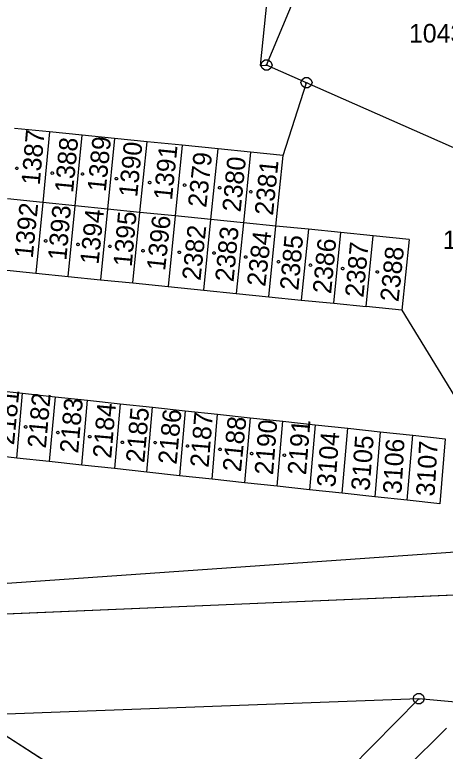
# Model space of a CAD drawing. Extents: x -777309 to -774195, y -1144706 to -1143600.
# Drawn here: x -775133.6 to -775094.2, y -1144462.3 to -1144394.9 of the extents above; entities that cross this region are included whole.
import ezdxf

# ---------------------------------------------------------------- set-up
doc = ezdxf.new("R2010")
doc.units = 0
for name, color, linetype in [('1', 7, 'Continuous'), ('11', 7, 'Continuous'), ('12', 7, 'Continuous'), ('2', 7, 'Continuous'), ('4', 7, 'Continuous'), ('5', 7, 'Continuous'), ('8', 7, 'Continuous')]:
    doc.layers.add(name, color=color, linetype=linetype)

msp = doc.modelspace()

# ---------------------------------------------------------------- linework, layer by layer
at = {"layer": '1'}
for p, q in [((-775110.57, -1144399.52), (-775105.05, -1144386.27)), ((-775110.56, -1144393.59), (-775111.16, -1144399.56)), ((-775111.16, -1144399.56), (-775110.57, -1144399.52)), ((-775106.91, -1144401.13), (-775110.57, -1144399.52)), ((-775109.06, -1144407.78), (-775106.91, -1144401.13)), ((-775080.73, -1144412.7), (-775106.91, -1144401.13)), ((-775130.42, -1144405.63), (-775133.63, -1144405.31)), ((-775130.42, -1144405.63), (-775131.06, -1144412.09)), ((-775127.45, -1144405.93), (-775130.42, -1144405.63)), ((-775128.09, -1144412.39), (-775127.45, -1144405.93)), ((-775124.49, -1144406.23), (-775127.45, -1144405.93)), ((-775124.49, -1144406.23), (-775125.13, -1144412.69)), ((-775121.51, -1144406.53), (-775124.49, -1144406.23)), ((-775122.16, -1144412.99), (-775121.51, -1144406.53)), ((-775118.28, -1144406.85), (-775121.51, -1144406.53)), ((-775118.28, -1144406.85), (-775118.93, -1144413.31)), ((-775115.01, -1144407.18), (-775118.28, -1144406.85)), ((-775115.66, -1144413.64), (-775115.01, -1144407.18)), ((-775112.03, -1144407.48), (-775115.01, -1144407.18)), ((-775112.03, -1144407.48), (-775112.69, -1144413.94)), ((-775109.06, -1144407.78), (-775112.03, -1144407.48)), ((-775109.71, -1144414.24), (-775109.06, -1144407.78)), ((-775131.06, -1144412.09), (-775134.27, -1144411.76)), ((-775131.06, -1144412.09), (-775131.7, -1144418.54)), ((-775128.09, -1144412.39), (-775131.06, -1144412.09)), ((-775128.74, -1144418.85), (-775128.09, -1144412.39)), ((-775125.13, -1144412.69), (-775128.09, -1144412.39)), ((-775125.13, -1144412.69), (-775125.77, -1144419.15)), ((-775122.16, -1144412.99), (-775125.13, -1144412.69)), ((-775122.8, -1144419.45), (-775122.16, -1144412.99)), ((-775118.93, -1144413.31), (-775122.16, -1144412.99)), ((-775118.93, -1144413.31), (-775119.58, -1144419.77)), ((-775115.66, -1144413.64), (-775118.93, -1144413.31)), ((-775116.31, -1144420.1), (-775115.66, -1144413.64)), ((-775112.69, -1144413.94), (-775115.66, -1144413.64)), ((-775112.69, -1144413.94), (-775113.34, -1144420.4)), ((-775109.71, -1144414.24), (-775112.69, -1144413.94)), ((-775110.37, -1144420.71), (-775109.71, -1144414.24)), ((-775106.74, -1144414.54), (-775109.71, -1144414.24)), ((-775106.74, -1144414.54), (-775107.39, -1144421.01)), ((-775103.77, -1144414.84), (-775106.74, -1144414.54)), ((-775104.42, -1144421.31), (-775103.77, -1144414.84)), ((-775100.8, -1144415.14), (-775103.77, -1144414.84)), ((-775101.45, -1144421.61), (-775100.8, -1144415.14)), ((-775097.53, -1144415.47), (-775100.8, -1144415.14)), ((-775097.53, -1144415.47), (-775098.18, -1144421.94)), ((-775134.91, -1144418.22), (-775131.7, -1144418.54)), ((-775131.7, -1144418.54), (-775128.74, -1144418.85)), ((-775128.74, -1144418.85), (-775125.77, -1144419.15)), ((-775125.77, -1144419.15), (-775122.8, -1144419.45)), ((-775122.8, -1144419.45), (-775119.58, -1144419.77)), ((-775119.58, -1144419.77), (-775116.31, -1144420.1)), ((-775116.31, -1144420.1), (-775113.34, -1144420.4)), ((-775113.34, -1144420.4), (-775110.37, -1144420.71)), ((-775110.37, -1144420.71), (-775107.39, -1144421.01)), ((-775107.39, -1144421.01), (-775104.42, -1144421.31)), ((-775104.42, -1144421.31), (-775101.45, -1144421.61)), ((-775098.18, -1144421.94), (-775101.45, -1144421.61)), ((-775098.18, -1144421.94), (-775093.37, -1144429.8)), ((-775135.87, -1144429.22), (-775132.9, -1144429.54)), ((-775133.43, -1144435.48), (-775132.9, -1144429.54)), ((-775132.9, -1144429.54), (-775129.92, -1144429.86)), ((-775129.92, -1144429.86), (-775130.46, -1144435.8)), ((-775129.92, -1144429.86), (-775126.95, -1144430.18)), ((-775127.48, -1144436.12), (-775126.95, -1144430.18)), ((-775126.95, -1144430.18), (-775123.97, -1144430.5)), ((-775123.97, -1144430.5), (-775124.5, -1144436.44)), ((-775123.97, -1144430.5), (-775121, -1144430.82)), ((-775121.52, -1144436.76), (-775121, -1144430.82)), ((-775121, -1144430.82), (-775118.02, -1144431.14)), ((-775118.02, -1144431.14), (-775118.54, -1144437.09)), ((-775118.02, -1144431.14), (-775115.05, -1144431.46)), ((-775115.56, -1144437.41), (-775115.05, -1144431.46)), ((-775115.05, -1144431.46), (-775112.07, -1144431.78)), ((-775112.07, -1144431.78), (-775112.58, -1144437.73)), ((-775112.07, -1144431.78), (-775109.09, -1144432.1)), ((-775109.61, -1144438.05), (-775109.09, -1144432.1)), ((-775109.09, -1144432.1), (-775106.12, -1144432.42)), ((-775106.12, -1144432.42), (-775106.63, -1144438.37)), ((-775106.12, -1144432.42), (-775103.14, -1144432.74)), ((-775103.65, -1144438.7), (-775103.14, -1144432.74)), ((-775103.14, -1144432.74), (-775100.17, -1144433.06)), ((-775100.17, -1144433.06), (-775100.67, -1144439.02)), ((-775100.17, -1144433.06), (-775097.19, -1144433.38)), ((-775097.69, -1144439.34), (-775097.19, -1144433.38)), ((-775097.19, -1144433.38), (-775094.22, -1144433.7)), ((-775094.22, -1144433.7), (-775094.71, -1144439.66)), ((-775133.43, -1144435.48), (-775136.41, -1144435.15)), ((-775130.46, -1144435.8), (-775133.43, -1144435.48)), ((-775127.48, -1144436.12), (-775130.46, -1144435.8)), ((-775124.5, -1144436.44), (-775127.48, -1144436.12)), ((-775121.52, -1144436.76), (-775124.5, -1144436.44)), ((-775118.54, -1144437.09), (-775121.52, -1144436.76)), ((-775115.56, -1144437.41), (-775118.54, -1144437.09)), ((-775112.58, -1144437.73), (-775115.56, -1144437.41)), ((-775109.61, -1144438.05), (-775112.58, -1144437.73)), ((-775106.63, -1144438.37), (-775109.61, -1144438.05)), ((-775103.65, -1144438.7), (-775106.63, -1144438.37)), ((-775100.67, -1144439.02), (-775103.65, -1144438.7)), ((-775097.69, -1144439.34), (-775100.67, -1144439.02)), ((-775094.71, -1144439.66), (-775097.69, -1144439.34)), ((-775157.8, -1144448.55), (-775092.84, -1144444.02)), ((-775088.39, -1144447.82), (-775138.01, -1144449.91)), ((-775096.64, -1144457.51), (-775137.35, -1144459.01)), ((-775113.36, -1144474.42), (-775096.64, -1144457.51)), ((-775076.86, -1144459.23), (-775096.64, -1144457.51)), ((-775137.35, -1144459.01), (-775115.39, -1144473.12))]:
    msp.add_line(p, q, dxfattribs=at)
at = {"layer": '11'}
for points in [[(-774795.44, -1144408.94), (-774821.85, -1144410.67), (-774824.22, -1144416.24), (-774826.54, -1144421.73), (-774829.24, -1144428.08), (-774832.66, -1144428.33), (-774870.21, -1144431.11), (-774871.96, -1144431.24), (-774890.46, -1144432.61), (-774957.77, -1144437.47), (-775003.31, -1144440.57), (-775006.9, -1144440.82), (-775032.95, -1144440.83), (-775037.63, -1144440.85), (-775036.16, -1144437.94), (-775069.78, -1144440.38), (-775071.04, -1144440.88), (-775088.39, -1144447.82), (-775138.01, -1144449.91)], [(-775137.35, -1144459.01), (-775115.39, -1144473.12), (-775113.36, -1144474.42), (-775120.76, -1144481.29), (-775159.15, -1144509.7)]]:
    msp.add_lwpolyline(points, dxfattribs=at)
at = {"layer": '12'}
for p, q in [((-775130.42, -1144405.63), (-775133.63, -1144405.31)), ((-775130.42, -1144405.63), (-775131.06, -1144412.09)), ((-775130.42, -1144405.63), (-775131.06, -1144412.09)), ((-775127.45, -1144405.93), (-775130.42, -1144405.63)), ((-775128.09, -1144412.39), (-775127.45, -1144405.93)), ((-775128.09, -1144412.39), (-775127.45, -1144405.93)), ((-775124.49, -1144406.23), (-775127.45, -1144405.93)), ((-775124.49, -1144406.23), (-775125.13, -1144412.69)), ((-775124.49, -1144406.23), (-775125.13, -1144412.69)), ((-775121.51, -1144406.53), (-775124.49, -1144406.23)), ((-775122.16, -1144412.99), (-775121.51, -1144406.53)), ((-775122.16, -1144412.99), (-775121.51, -1144406.53)), ((-775118.28, -1144406.85), (-775121.51, -1144406.53)), ((-775118.28, -1144406.85), (-775118.93, -1144413.31)), ((-775118.28, -1144406.85), (-775118.93, -1144413.31)), ((-775115.01, -1144407.18), (-775118.28, -1144406.85)), ((-775115.66, -1144413.64), (-775115.01, -1144407.18)), ((-775115.66, -1144413.64), (-775115.01, -1144407.18)), ((-775112.03, -1144407.48), (-775115.01, -1144407.18)), ((-775112.03, -1144407.48), (-775112.69, -1144413.94)), ((-775112.03, -1144407.48), (-775112.69, -1144413.94)), ((-775109.06, -1144407.78), (-775112.03, -1144407.48)), ((-775109.71, -1144414.24), (-775109.06, -1144407.78)), ((-775131.06, -1144412.09), (-775134.27, -1144411.76)), ((-775131.06, -1144412.09), (-775134.27, -1144411.76)), ((-775131.06, -1144412.09), (-775131.7, -1144418.54)), ((-775131.06, -1144412.09), (-775131.7, -1144418.54)), ((-775128.09, -1144412.39), (-775131.06, -1144412.09)), ((-775128.09, -1144412.39), (-775131.06, -1144412.09)), ((-775128.74, -1144418.85), (-775128.09, -1144412.39)), ((-775128.74, -1144418.85), (-775128.09, -1144412.39)), ((-775125.13, -1144412.69), (-775128.09, -1144412.39)), ((-775125.13, -1144412.69), (-775128.09, -1144412.39)), ((-775125.13, -1144412.69), (-775125.77, -1144419.15)), ((-775125.13, -1144412.69), (-775125.77, -1144419.15)), ((-775122.16, -1144412.99), (-775125.13, -1144412.69)), ((-775122.16, -1144412.99), (-775125.13, -1144412.69)), ((-775122.8, -1144419.45), (-775122.16, -1144412.99)), ((-775122.8, -1144419.45), (-775122.16, -1144412.99)), ((-775118.93, -1144413.31), (-775122.16, -1144412.99)), ((-775118.93, -1144413.31), (-775122.16, -1144412.99)), ((-775118.93, -1144413.31), (-775119.58, -1144419.77)), ((-775118.93, -1144413.31), (-775119.58, -1144419.77)), ((-775115.66, -1144413.64), (-775118.93, -1144413.31)), ((-775115.66, -1144413.64), (-775118.93, -1144413.31)), ((-775116.31, -1144420.1), (-775115.66, -1144413.64)), ((-775116.31, -1144420.1), (-775115.66, -1144413.64)), ((-775112.69, -1144413.94), (-775115.66, -1144413.64)), ((-775112.69, -1144413.94), (-775115.66, -1144413.64)), ((-775112.69, -1144413.94), (-775113.34, -1144420.4)), ((-775112.69, -1144413.94), (-775113.34, -1144420.4)), ((-775109.71, -1144414.24), (-775112.69, -1144413.94)), ((-775109.71, -1144414.24), (-775112.69, -1144413.94)), ((-775110.37, -1144420.71), (-775109.71, -1144414.24)), ((-775110.37, -1144420.71), (-775109.71, -1144414.24)), ((-775106.74, -1144414.54), (-775109.71, -1144414.24)), ((-775106.74, -1144414.54), (-775107.39, -1144421.01)), ((-775106.74, -1144414.54), (-775107.39, -1144421.01)), ((-775103.77, -1144414.84), (-775106.74, -1144414.54)), ((-775104.42, -1144421.31), (-775103.77, -1144414.84)), ((-775104.42, -1144421.31), (-775103.77, -1144414.84)), ((-775100.8, -1144415.14), (-775103.77, -1144414.84)), ((-775101.45, -1144421.61), (-775100.8, -1144415.14)), ((-775101.45, -1144421.61), (-775100.8, -1144415.14)), ((-775097.53, -1144415.47), (-775100.8, -1144415.14)), ((-775097.53, -1144415.47), (-775098.18, -1144421.94)), ((-775134.91, -1144418.22), (-775131.7, -1144418.54)), ((-775131.7, -1144418.54), (-775128.74, -1144418.85)), ((-775128.74, -1144418.85), (-775125.77, -1144419.15)), ((-775125.77, -1144419.15), (-775122.8, -1144419.45)), ((-775122.8, -1144419.45), (-775119.58, -1144419.77)), ((-775119.58, -1144419.77), (-775116.31, -1144420.1)), ((-775116.31, -1144420.1), (-775113.34, -1144420.4)), ((-775113.34, -1144420.4), (-775110.37, -1144420.71)), ((-775110.37, -1144420.71), (-775107.39, -1144421.01)), ((-775107.39, -1144421.01), (-775104.42, -1144421.31)), ((-775104.42, -1144421.31), (-775101.45, -1144421.61)), ((-775098.18, -1144421.94), (-775101.45, -1144421.61)), ((-775135.87, -1144429.22), (-775132.9, -1144429.54)), ((-775133.43, -1144435.48), (-775132.9, -1144429.54)), ((-775133.43, -1144435.48), (-775132.9, -1144429.54)), ((-775132.9, -1144429.54), (-775129.92, -1144429.86)), ((-775129.92, -1144429.86), (-775130.46, -1144435.8)), ((-775129.92, -1144429.86), (-775130.46, -1144435.8)), ((-775129.92, -1144429.86), (-775126.95, -1144430.18)), ((-775127.48, -1144436.12), (-775126.95, -1144430.18)), ((-775127.48, -1144436.12), (-775126.95, -1144430.18)), ((-775126.95, -1144430.18), (-775123.97, -1144430.5)), ((-775123.97, -1144430.5), (-775124.5, -1144436.44)), ((-775123.97, -1144430.5), (-775124.5, -1144436.44)), ((-775123.97, -1144430.5), (-775121, -1144430.82)), ((-775121.52, -1144436.76), (-775121, -1144430.82)), ((-775121.52, -1144436.76), (-775121, -1144430.82)), ((-775121, -1144430.82), (-775118.02, -1144431.14)), ((-775118.02, -1144431.14), (-775118.54, -1144437.09)), ((-775118.02, -1144431.14), (-775118.54, -1144437.09)), ((-775118.02, -1144431.14), (-775115.05, -1144431.46)), ((-775115.56, -1144437.41), (-775115.05, -1144431.46)), ((-775115.56, -1144437.41), (-775115.05, -1144431.46)), ((-775115.05, -1144431.46), (-775112.07, -1144431.78)), ((-775112.07, -1144431.78), (-775112.58, -1144437.73)), ((-775112.07, -1144431.78), (-775112.58, -1144437.73)), ((-775112.07, -1144431.78), (-775109.09, -1144432.1)), ((-775109.61, -1144438.05), (-775109.09, -1144432.1)), ((-775109.61, -1144438.05), (-775109.09, -1144432.1)), ((-775109.09, -1144432.1), (-775106.12, -1144432.42)), ((-775106.12, -1144432.42), (-775106.63, -1144438.37)), ((-775133.43, -1144435.48), (-775136.41, -1144435.15)), ((-775130.46, -1144435.8), (-775133.43, -1144435.48)), ((-775127.48, -1144436.12), (-775130.46, -1144435.8)), ((-775124.5, -1144436.44), (-775127.48, -1144436.12)), ((-775121.52, -1144436.76), (-775124.5, -1144436.44)), ((-775118.54, -1144437.09), (-775121.52, -1144436.76)), ((-775115.56, -1144437.41), (-775118.54, -1144437.09)), ((-775112.58, -1144437.73), (-775115.56, -1144437.41)), ((-775109.61, -1144438.05), (-775112.58, -1144437.73)), ((-775106.63, -1144438.37), (-775109.61, -1144438.05))]:
    msp.add_line(p, q, dxfattribs=at)
at = {"layer": '4'}
msp.add_line((-775094.1, -1144460.2), (-775111.21, -1144477.04), dxfattribs=at)
at = {"layer": '5'}
for points in [[(-775133.43, -1144408.846), (-775133.363, -1144408.86), (-775133.329, -1144408.92), (-775133.316, -1144408.96), (-775133.329, -1144409.02), (-775133.383, -1144409.067), (-775133.43, -1144409.074), (-775133.49, -1144409.054), (-775133.531, -1144409.014), (-775133.544, -1144408.96), (-775133.531, -1144408.9), (-775133.477, -1144408.853)], [(-775130.18, -1144409.286), (-775130.113, -1144409.299), (-775130.079, -1144409.36), (-775130.066, -1144409.4), (-775130.079, -1144409.46), (-775130.133, -1144409.507), (-775130.18, -1144409.514), (-775130.24, -1144409.494), (-775130.281, -1144409.454), (-775130.294, -1144409.4), (-775130.281, -1144409.34), (-775130.227, -1144409.293)], [(-775127.41, -1144409.366), (-775127.343, -1144409.38), (-775127.309, -1144409.44), (-775127.296, -1144409.48), (-775127.309, -1144409.54), (-775127.363, -1144409.587), (-775127.41, -1144409.594), (-775127.47, -1144409.574), (-775127.511, -1144409.534), (-775127.524, -1144409.48), (-775127.511, -1144409.42), (-775127.457, -1144409.373)], [(-775124.31, -1144409.796), (-775124.243, -1144409.809), (-775124.21, -1144409.87), (-775124.196, -1144409.91), (-775124.21, -1144409.97), (-775124.263, -1144410.017), (-775124.31, -1144410.024), (-775124.37, -1144410.004), (-775124.411, -1144409.964), (-775124.424, -1144409.91), (-775124.411, -1144409.85), (-775124.357, -1144409.803)], [(-775121.27, -1144410.146), (-775121.203, -1144410.16), (-775121.17, -1144410.22), (-775121.156, -1144410.26), (-775121.17, -1144410.32), (-775121.223, -1144410.367), (-775121.27, -1144410.374), (-775121.33, -1144410.354), (-775121.37, -1144410.314), (-775121.384, -1144410.26), (-775121.37, -1144410.2), (-775121.317, -1144410.153)], [(-775118.07, -1144410.386), (-775118.003, -1144410.4), (-775117.969, -1144410.46), (-775117.956, -1144410.5), (-775117.969, -1144410.56), (-775118.023, -1144410.607), (-775118.07, -1144410.614), (-775118.13, -1144410.594), (-775118.171, -1144410.554), (-775118.184, -1144410.5), (-775118.171, -1144410.44), (-775118.117, -1144410.393)], [(-775114.86, -1144410.626), (-775114.793, -1144410.64), (-775114.759, -1144410.7), (-775114.746, -1144410.74), (-775114.759, -1144410.8), (-775114.813, -1144410.847), (-775114.86, -1144410.854), (-775114.92, -1144410.834), (-775114.961, -1144410.794), (-775114.974, -1144410.74), (-775114.961, -1144410.68), (-775114.907, -1144410.633)], [(-775112.01, -1144410.996), (-775111.943, -1144411.01), (-775111.91, -1144411.07), (-775111.896, -1144411.11), (-775111.91, -1144411.17), (-775111.963, -1144411.217), (-775112.01, -1144411.224), (-775112.07, -1144411.204), (-775112.111, -1144411.164), (-775112.124, -1144411.11), (-775112.111, -1144411.05), (-775112.057, -1144411.003)], [(-775130.79, -1144415.486), (-775130.723, -1144415.5), (-775130.69, -1144415.56), (-775130.676, -1144415.6), (-775130.69, -1144415.66), (-775130.743, -1144415.707), (-775130.79, -1144415.714), (-775130.85, -1144415.694), (-775130.891, -1144415.654), (-775130.904, -1144415.6), (-775130.891, -1144415.54), (-775130.837, -1144415.493)], [(-775127.82, -1144415.816), (-775127.753, -1144415.829), (-775127.719, -1144415.89), (-775127.706, -1144415.93), (-775127.719, -1144415.99), (-775127.773, -1144416.037), (-775127.82, -1144416.044), (-775127.88, -1144416.024), (-775127.921, -1144415.984), (-775127.934, -1144415.93), (-775127.921, -1144415.87), (-775127.867, -1144415.823)], [(-775124.91, -1144415.986), (-775124.843, -1144416), (-775124.809, -1144416.06), (-775124.796, -1144416.1), (-775124.809, -1144416.16), (-775124.863, -1144416.207), (-775124.91, -1144416.214), (-775124.97, -1144416.194), (-775125.011, -1144416.154), (-775125.024, -1144416.1), (-775125.011, -1144416.04), (-775124.957, -1144415.993)], [(-775121.87, -1144416.396), (-775121.803, -1144416.41), (-775121.769, -1144416.47), (-775121.756, -1144416.51), (-775121.769, -1144416.57), (-775121.823, -1144416.617), (-775121.87, -1144416.624), (-775121.93, -1144416.604), (-775121.971, -1144416.564), (-775121.984, -1144416.51), (-775121.971, -1144416.45), (-775121.917, -1144416.403)], [(-775118.56, -1144416.526), (-775118.493, -1144416.539), (-775118.46, -1144416.6), (-775118.446, -1144416.64), (-775118.46, -1144416.7), (-775118.513, -1144416.747), (-775118.56, -1144416.754), (-775118.62, -1144416.734), (-775118.66, -1144416.694), (-775118.674, -1144416.64), (-775118.66, -1144416.58), (-775118.607, -1144416.533)], [(-775115.38, -1144416.596), (-775115.313, -1144416.61), (-775115.28, -1144416.67), (-775115.266, -1144416.71), (-775115.28, -1144416.77), (-775115.333, -1144416.817), (-775115.38, -1144416.824), (-775115.44, -1144416.804), (-775115.481, -1144416.764), (-775115.494, -1144416.71), (-775115.481, -1144416.65), (-775115.427, -1144416.603)], [(-775112.48, -1144416.966), (-775112.413, -1144416.98), (-775112.38, -1144417.04), (-775112.366, -1144417.08), (-775112.38, -1144417.14), (-775112.433, -1144417.187), (-775112.48, -1144417.194), (-775112.54, -1144417.174), (-775112.581, -1144417.134), (-775112.594, -1144417.08), (-775112.581, -1144417.02), (-775112.527, -1144416.973)], [(-775109.48, -1144417.396), (-775109.413, -1144417.41), (-775109.38, -1144417.47), (-775109.366, -1144417.51), (-775109.38, -1144417.57), (-775109.433, -1144417.617), (-775109.48, -1144417.624), (-775109.54, -1144417.604), (-775109.581, -1144417.564), (-775109.594, -1144417.51), (-775109.581, -1144417.45), (-775109.527, -1144417.403)], [(-775106.55, -1144417.706), (-775106.483, -1144417.72), (-775106.45, -1144417.78), (-775106.436, -1144417.82), (-775106.45, -1144417.88), (-775106.503, -1144417.927), (-775106.55, -1144417.934), (-775106.61, -1144417.914), (-775106.65, -1144417.874), (-775106.664, -1144417.82), (-775106.65, -1144417.76), (-775106.597, -1144417.713)], [(-775103.61, -1144418.016), (-775103.543, -1144418.029), (-775103.509, -1144418.09), (-775103.496, -1144418.13), (-775103.509, -1144418.19), (-775103.563, -1144418.237), (-775103.61, -1144418.244), (-775103.67, -1144418.224), (-775103.711, -1144418.184), (-775103.724, -1144418.13), (-775103.711, -1144418.07), (-775103.657, -1144418.023)], [(-775100.43, -1144418.326), (-775100.363, -1144418.34), (-775100.329, -1144418.4), (-775100.316, -1144418.44), (-775100.329, -1144418.5), (-775100.383, -1144418.547), (-775100.43, -1144418.554), (-775100.49, -1144418.534), (-775100.531, -1144418.494), (-775100.544, -1144418.44), (-775100.531, -1144418.38), (-775100.477, -1144418.333)], [(-775132.62, -1144432.506), (-775132.553, -1144432.52), (-775132.519, -1144432.58), (-775132.506, -1144432.62), (-775132.519, -1144432.68), (-775132.573, -1144432.727), (-775132.62, -1144432.734), (-775132.68, -1144432.714), (-775132.721, -1144432.674), (-775132.734, -1144432.62), (-775132.721, -1144432.56), (-775132.667, -1144432.513)], [(-775129.67, -1144433.026), (-775129.603, -1144433.039), (-775129.569, -1144433.1), (-775129.556, -1144433.14), (-775129.569, -1144433.2), (-775129.623, -1144433.247), (-775129.67, -1144433.254), (-775129.73, -1144433.234), (-775129.771, -1144433.194), (-775129.784, -1144433.14), (-775129.771, -1144433.08), (-775129.717, -1144433.033)], [(-775126.75, -1144433.406), (-775126.683, -1144433.42), (-775126.65, -1144433.48), (-775126.636, -1144433.52), (-775126.65, -1144433.58), (-775126.703, -1144433.627), (-775126.75, -1144433.634), (-775126.81, -1144433.614), (-775126.851, -1144433.574), (-775126.864, -1144433.52), (-775126.851, -1144433.46), (-775126.797, -1144433.413)], [(-775123.77, -1144433.926), (-775123.703, -1144433.94), (-775123.67, -1144434), (-775123.656, -1144434.04), (-775123.67, -1144434.1), (-775123.723, -1144434.147), (-775123.77, -1144434.154), (-775123.83, -1144434.134), (-775123.87, -1144434.094), (-775123.884, -1144434.04), (-775123.87, -1144433.98), (-775123.817, -1144433.933)], [(-775120.77, -1144433.946), (-775120.703, -1144433.96), (-775120.67, -1144434.02), (-775120.656, -1144434.06), (-775120.67, -1144434.12), (-775120.723, -1144434.167), (-775120.77, -1144434.174), (-775120.83, -1144434.154), (-775120.871, -1144434.114), (-775120.884, -1144434.06), (-775120.871, -1144434), (-775120.817, -1144433.953)], [(-775117.8, -1144434.256), (-775117.733, -1144434.27), (-775117.7, -1144434.33), (-775117.686, -1144434.37), (-775117.7, -1144434.43), (-775117.753, -1144434.477), (-775117.8, -1144434.484), (-775117.86, -1144434.464), (-775117.901, -1144434.424), (-775117.914, -1144434.37), (-775117.901, -1144434.31), (-775117.847, -1144434.263)], [(-775114.84, -1144434.566), (-775114.773, -1144434.579), (-775114.739, -1144434.64), (-775114.726, -1144434.68), (-775114.739, -1144434.74), (-775114.793, -1144434.787), (-775114.84, -1144434.794), (-775114.9, -1144434.774), (-775114.941, -1144434.734), (-775114.954, -1144434.68), (-775114.941, -1144434.62), (-775114.887, -1144434.573)], [(-775111.94, -1144434.946), (-775111.873, -1144434.96), (-775111.84, -1144435.02), (-775111.826, -1144435.06), (-775111.84, -1144435.12), (-775111.893, -1144435.167), (-775111.94, -1144435.174), (-775112, -1144435.154), (-775112.04, -1144435.114), (-775112.054, -1144435.06), (-775112.04, -1144435), (-775111.987, -1144434.953)], [(-775108.94, -1144435.096), (-775108.873, -1144435.11), (-775108.84, -1144435.17), (-775108.826, -1144435.21), (-775108.84, -1144435.27), (-775108.893, -1144435.317), (-775108.94, -1144435.324), (-775109, -1144435.304), (-775109.04, -1144435.264), (-775109.054, -1144435.21), (-775109.04, -1144435.15), (-775108.987, -1144435.103)]]:
    msp.add_lwpolyline(points, close=True, dxfattribs=at)
at = {"layer": '8'}
for p, q in [((-775110.69, -1144399.52), (-775110.45, -1144399.52)), ((-775107.03, -1144401.13), (-775106.79, -1144401.13)), ((-775096.76, -1144457.51), (-775096.52, -1144457.51))]:
    msp.add_line(p, q, dxfattribs=at)
for points in [[(-775110.42, -1144399.04), (-775110.17, -1144399.22), (-775110.07, -1144399.51), (-775110.17, -1144399.8), (-775110.42, -1144399.98), (-775110.73, -1144399.98), (-775110.98, -1144399.8), (-775111.08, -1144399.51), (-775110.98, -1144399.22), (-775110.73, -1144399.04)], [(-775106.76, -1144400.65), (-775106.51, -1144400.83), (-775106.41, -1144401.12), (-775106.51, -1144401.41), (-775106.76, -1144401.59), (-775107.07, -1144401.59), (-775107.32, -1144401.41), (-775107.42, -1144401.12), (-775107.32, -1144400.83), (-775107.07, -1144400.65)], [(-775096.49, -1144457.03), (-775096.24, -1144457.21), (-775096.14, -1144457.5), (-775096.24, -1144457.79), (-775096.49, -1144457.97), (-775096.8, -1144457.97), (-775097.05, -1144457.79), (-775097.15, -1144457.5), (-775097.05, -1144457.21), (-775096.8, -1144457.03)]]:
    msp.add_lwpolyline(points, close=True, dxfattribs=at)

# ---------------------------------------------------------------- texts
at = {"layer": '2'}
for s, p in [('1043/36', (-775097.537, -1144397.45)), ('1043/60', (-775094.437, -1144416.35))]:
    msp.add_text(s, height=1.7, dxfattribs=at).set_placement(p)
for s, rotation, p in [('1387', 84.79775, (-775131.334, -1144410.539)), ('1388', 84.51127, (-775128.282, -1144411.249)), ('1389', 84.28209, (-775125.291, -1144411.159)), ('1390', 84.39668, (-775122.412, -1144411.649)), ('1391', 84.1102, (-775119.23, -1144411.929)), ('2379', 83.70913, (-775116.094, -1144412.604)), ('2380', 84.33939, (-775112.947, -1144413.014)), ('2381', 84.1102, (-775109.986, -1144413.324)), ('1392', 84.28209, (-775131.971, -1144417.239)), ('1393', 85.02694, (-775128.896, -1144417.439)), ('1394', 84.28209, (-775125.951, -1144417.809)), ('1395', 84.74046, (-775122.914, -1144418.009)), ('1396', 83.93832, (-775119.859, -1144418.389)), ('2382', 83.82373, (-775116.624, -1144419.284)), ('2383', 84.45398, (-775113.597, -1144419.404)), ('2384', 83.36536, (-775110.693, -1144419.834)), ('2385', 84.85505, (-775107.669, -1144420.174)), ('2386', 84.45398, (-775104.667, -1144420.484)), ('2387', 84.56857, (-775101.708, -1144420.824)), ('2388', 84.2248, (-775098.496, -1144421.234)), ('2181', 84.33939, (-775133.687, -1144434.324)), ('2182', 84.91235, (-775130.769, -1144434.624)), ('2183', 84.91235, (-775127.819, -1144435.084)), ('2184', 85.02694, (-775124.789, -1144435.543)), ('2185', 84.91235, (-775121.759, -1144435.954)), ('2186', 84.74046, (-775118.808, -1144436.104)), ('2187', 85.37071, (-775115.881, -1144436.383)), ('2188', 84.2248, (-775112.916, -1144436.784)), ('2190', 85.42801, (-775109.981, -1144437.063)), ('2191', 85.37071, (-775106.961, -1144437.063)), ('3104', 85.59989, (-775104.285, -1144438.192)), ('3105', 85.42801, (-775101.156, -1144438.508)), ('3106', 86.63122, (-775098.232, -1144438.795)), ('3107', 86.57392, (-775095.202, -1144439.015))]:
    msp.add_text(s, height=1.7, rotation=rotation, dxfattribs=at).set_placement(p)

doc.saveas('drawing.dxf')
